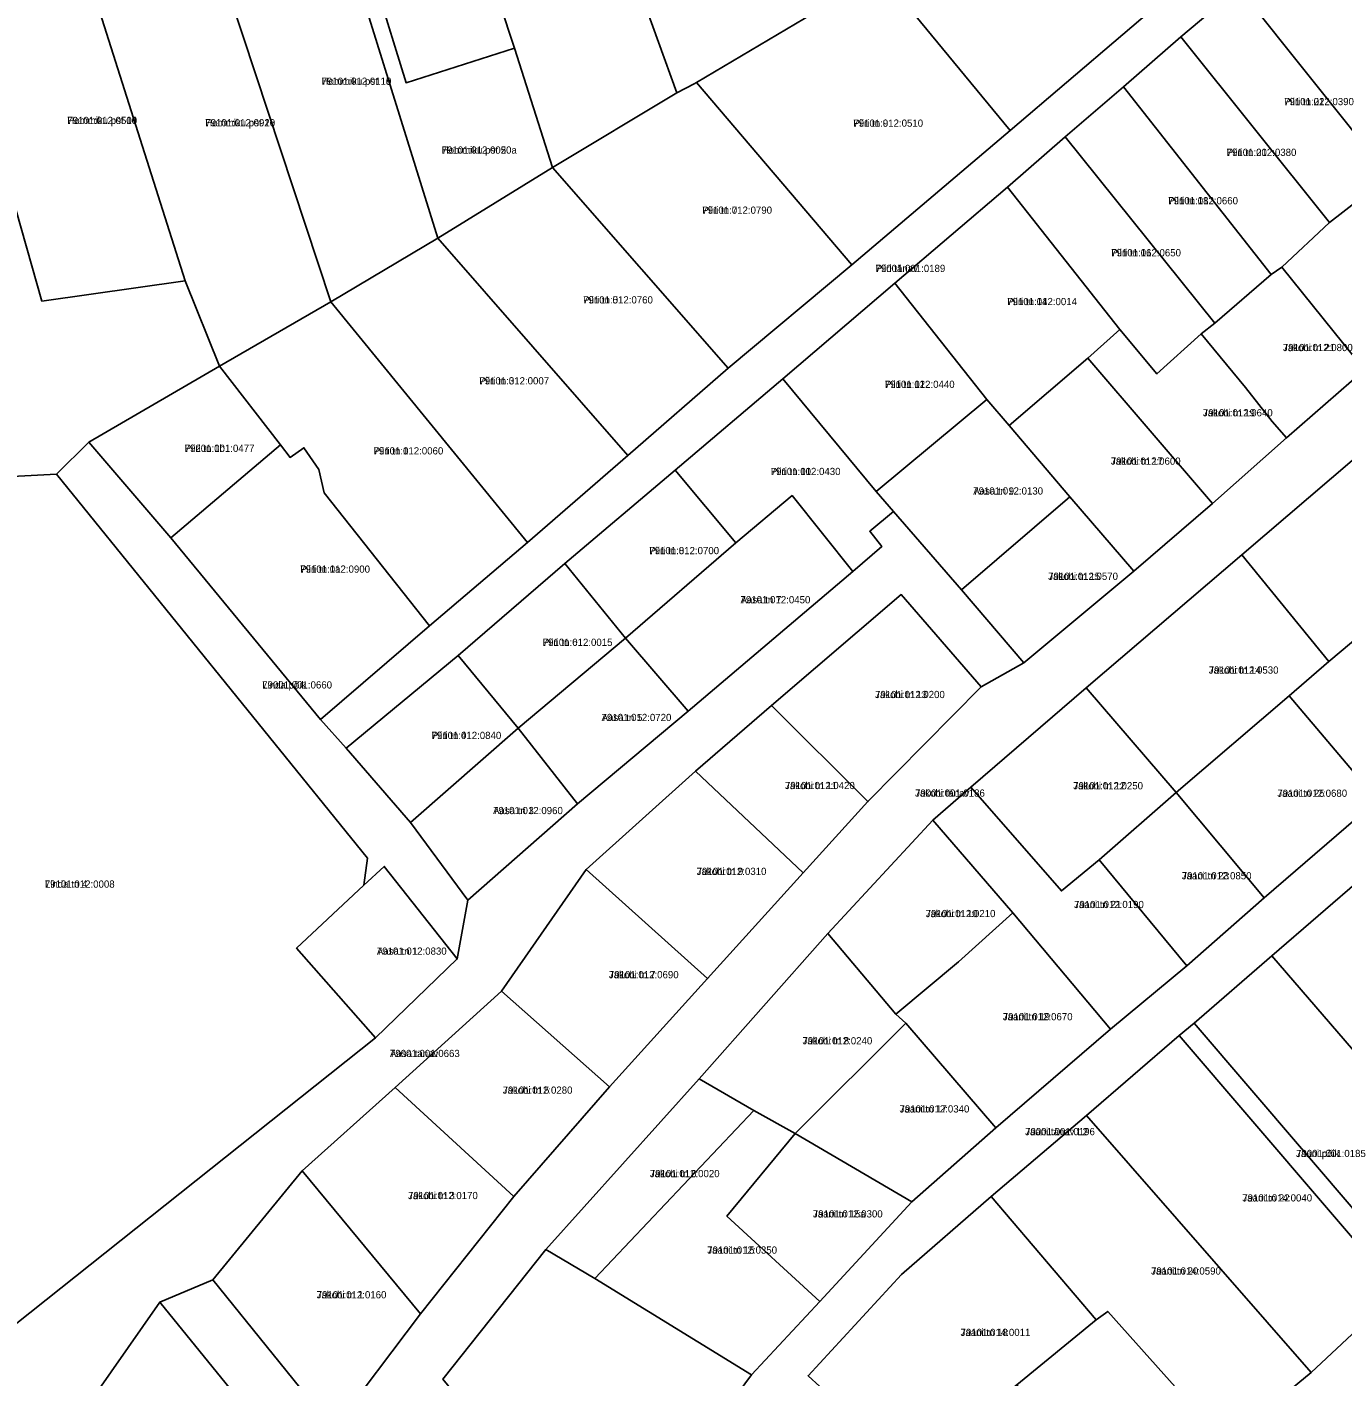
# Model space of a CAD drawing. Extents: x 587616 to 632239, y 6547421 to 6574977.
# Drawn here: x 612329 to 612602.3, y 6570710.7 to 6570991.1 of the extents above; entities that cross this region are included whole.
import ezdxf

# ---------------------------------------------------------------- set-up
doc = ezdxf.new("R2010")
doc.units = 0
for name, color, linetype in [('L_AADRESS', 7, 'Continuous'), ('PIIR', 7, 'Continuous'), ('TUNNUS', 7, 'Continuous')]:
    doc.layers.add(name, color=color, linetype=linetype)

msp = doc.modelspace()

# ---------------------------------------------------------------- linework, layer by layer
at = {"layer": 'PIIR'}
for points in [[(612389.94, 6570847.26), (612412.64, 6570866.69), (612433.02, 6570884.05), (612453.81, 6570902.08), (612474.71, 6570920.29), (612500.42, 6570941.76), (612533.3, 6570969.66), (612568.39, 6570999.66), (612614.03, 6571039.16), (612617.14, 6571030.36), (612593.08, 6571009.5), (612580.84, 6570999.28), (612568.76, 6570989.08), (612556.88, 6570978.73), (612544.75, 6570968.32), (612532.76, 6570957.89), (612509.3, 6570937.93), (612486.02, 6570918.07), (612463.66, 6570899.06), (612440.76, 6570879.66), (612418.55, 6570860.59), (612395.3, 6570841.33)], [(612478.97, 6571038.64), (612496.16, 6570996.2), (612468.11, 6570979.63), (612467.62, 6570979.34), (612464, 6570977.46), (612445, 6571030.17)], [(612430.31, 6570986.72), (612417.96, 6571024.07), (612445, 6571030.17), (612464, 6570977.46), (612438.2, 6570961.93)], [(612506.46, 6571002.17), (612513.42, 6571006.83), (612535.92, 6571019.94), (612550.68, 6571028.77), (612568.39, 6570999.66), (612533.3, 6570969.66)], [(612417.96, 6571024.07), (612430.31, 6570986.72), (612407.77, 6570979.56), (612395.44, 6571019.47)], [(612392.11, 6571018.7), (612414.38, 6570947.27), (612392.14, 6570934.06), (612365.99, 6571013.12)], [(612392.11, 6571018.7), (612395.44, 6571019.47), (612407.77, 6570979.56), (612430.31, 6570986.72), (612438.2, 6570961.93), (612414.38, 6570947.27)], [(612339.92, 6571007.58), (612365.99, 6571013.12), (612392.14, 6570934.06), (612368.95, 6570920.7), (612361.85, 6570938.43)], [(612361.85, 6570938.43), (612332.07, 6570934.19), (612312.85, 6571001.74), (612339.92, 6571007.58)], [(612593.08, 6571009.5), (612604.88, 6570994.7), (612616.39, 6570979.98), (612623.73, 6570970.6), (612611.71, 6570960.58), (612580.84, 6570999.28)], [(612252.57, 6570990.08), (612312.2, 6571004.01), (612312.85, 6571001.74), (612332.07, 6570934.19), (612361.85, 6570938.43), (612368.95, 6570920.7), (612341.84, 6570904.87), (612335.14, 6570898.25), (612273.14, 6570894.97)], [(612468.11, 6570979.63), (612496.16, 6570996.2), (612506.46, 6571002.17), (612533.3, 6570969.66), (612500.42, 6570941.76)], [(612580.84, 6570999.28), (612611.71, 6570960.58), (612605.79, 6570955.33), (612599.68, 6570950.51), (612568.76, 6570989.08)], [(612556.88, 6570978.73), (612568.76, 6570989.08), (612599.68, 6570950.51), (612589.74, 6570941.27), (612587.53, 6570939.73)], [(612464, 6570977.46), (612467.62, 6570979.34), (612468.11, 6570979.63), (612500.42, 6570941.76), (612474.71, 6570920.29), (612438.2, 6570961.93)], [(612556.88, 6570978.73), (612587.53, 6570939.73), (612575.82, 6570929.61), (612544.75, 6570968.32)], [(612544.75, 6570968.32), (612575.82, 6570929.61), (612573.01, 6570927.38), (612563.78, 6570919.07), (612556.06, 6570928.32), (612532.76, 6570957.89)], [(612438.2, 6570961.93), (612474.71, 6570920.29), (612453.81, 6570902.08), (612414.38, 6570947.27)], [(612532.76, 6570957.89), (612556.06, 6570928.32), (612549.43, 6570922.33), (612533.1, 6570908.38), (612528.47, 6570913.77), (612509.3, 6570937.93)], [(612599.68, 6570950.51), (612605.79, 6570955.33), (612623.43, 6570933.68), (612606.95, 6570919.88), (612589.74, 6570941.27)], [(612414.38, 6570947.27), (612453.81, 6570902.08), (612433.02, 6570884.05), (612392.14, 6570934.06)], [(612582.22, 6570916.21), (612573.01, 6570927.38), (612575.82, 6570929.61), (612587.53, 6570939.73), (612589.74, 6570941.27), (612606.95, 6570919.88), (612590.75, 6570905.76), (612587.73, 6570909.16)], [(612486.02, 6570918.07), (612509.3, 6570937.93), (612528.47, 6570913.77), (612505.42, 6570894.61)], [(612368.95, 6570920.7), (612392.14, 6570934.06), (612433.02, 6570884.05), (612412.64, 6570866.69), (612390.71, 6570894.39), (612389.66, 6570899.21), (612386.53, 6570903.72), (612383.64, 6570901.71), (612381.63, 6570904.32)], [(612556.06, 6570928.32), (612563.78, 6570919.07), (612573.01, 6570927.38), (612582.22, 6570916.21), (612587.73, 6570909.16), (612590.75, 6570905.76), (612575.34, 6570892.15), (612549.43, 6570922.33)], [(612341.84, 6570904.87), (612368.95, 6570920.7), (612381.63, 6570904.32), (612358.88, 6570885.02)], [(612533.1, 6570908.38), (612549.43, 6570922.33), (612575.34, 6570892.15), (612559, 6570878.1), (612545.72, 6570893.5)], [(612505.42, 6570894.61), (612509.02, 6570890.5), (612504.11, 6570886.39), (612506.63, 6570883.23), (612500.63, 6570878.04), (612487.97, 6570893.79), (612476.29, 6570884), (612463.66, 6570899.06), (612486.02, 6570918.07)], [(612509.02, 6570890.5), (612505.42, 6570894.61), (612528.47, 6570913.77), (612533.1, 6570908.38), (612545.72, 6570893.5), (612523.21, 6570874.23)], [(612420.6, 6570809.75), (612418.39, 6570797.51), (612403.21, 6570816.74), (612398.97, 6570812.81), (612399.71, 6570818.48), (612335.14, 6570898.25), (612341.84, 6570904.87), (612358.88, 6570885.02), (612389.94, 6570847.26), (612395.3, 6570841.33), (612408.65, 6570825.83)], [(612412.64, 6570866.69), (612389.94, 6570847.26), (612358.88, 6570885.02), (612381.63, 6570904.32), (612383.64, 6570901.71), (612386.53, 6570903.72), (612389.66, 6570899.21), (612390.71, 6570894.39)], [(612622.96, 6570879.59), (612615.37, 6570872.59), (612599.5, 6570859.29), (612581.45, 6570881.46), (612604.85, 6570901.47)], [(612335.14, 6570898.25), (612399.71, 6570818.48), (612398.97, 6570812.81), (612384.99, 6570799.78), (612401.38, 6570781.15), (612292.21, 6570694.33), (612263.99, 6570725.29), (612272.88, 6570759.5), (612277.84, 6570786.63), (612273.67, 6570884.71), (612273.14, 6570894.97)], [(612440.76, 6570879.66), (612463.66, 6570899.06), (612476.29, 6570884), (612453.38, 6570864.16)], [(612453.38, 6570864.16), (612476.29, 6570884), (612487.97, 6570893.79), (612500.63, 6570878.04), (612466.4, 6570849)], [(612523.21, 6570874.23), (612545.72, 6570893.5), (612559, 6570878.1), (612536.12, 6570859.04)], [(612549.06, 6570853.84), (612581.45, 6570881.46), (612599.5, 6570859.29), (612591.26, 6570852.2), (612567.82, 6570832.13)], [(612440.76, 6570879.66), (612453.38, 6570864.16), (612431.06, 6570845.45), (612418.55, 6570860.59)], [(612483.69, 6570850.19), (612510.65, 6570873.21), (612527.28, 6570854.08), (612503.75, 6570830.21)], [(612609.62, 6570830.53), (612591.26, 6570852.2), (612599.5, 6570859.29), (612615.37, 6570872.59), (612633.51, 6570850.98)], [(612431.06, 6570845.45), (612453.38, 6570864.16), (612466.4, 6570849), (612443.41, 6570829.72)], [(612408.65, 6570825.83), (612395.3, 6570841.33), (612418.55, 6570860.59), (612431.06, 6570845.45)], [(612525.1, 6570833.23), (612549.06, 6570853.84), (612567.82, 6570832.13), (612551.82, 6570818.11), (612543.94, 6570811.66)], [(612467.92, 6570836.5), (612483.69, 6570850.19), (612503.75, 6570830.21), (612490.29, 6570815.41)], [(612567.82, 6570832.13), (612591.26, 6570852.2), (612609.62, 6570830.53), (612586.07, 6570810.2)], [(612408.65, 6570825.83), (612431.06, 6570845.45), (612443.41, 6570829.72), (612420.6, 6570809.75)], [(612467.92, 6570836.5), (612490.29, 6570815.41), (612470.43, 6570793.43), (612445.15, 6570816.07)], [(612517.22, 6570826.32), (612525.1, 6570833.23), (612543.94, 6570811.66), (612551.82, 6570818.11), (612569.99, 6570796.06), (612554.12, 6570782.92), (612533.88, 6570807.11)], [(612567.82, 6570832.13), (612586.07, 6570810.2), (612569.99, 6570796.06), (612551.82, 6570818.11)], [(612533.88, 6570807.11), (612522.59, 6570796.94), (612509.51, 6570786.07), (612495.43, 6570802.77), (612517.22, 6570826.32)], [(612384.99, 6570799.78), (612398.97, 6570812.81), (612403.21, 6570816.74), (612418.39, 6570797.51), (612401.38, 6570781.15)], [(612445.15, 6570816.07), (612470.43, 6570793.43), (612450.02, 6570770.92), (612427.61, 6570790.85)], [(612606.95, 6570814.75), (612636, 6570780.77), (612652.62, 6570761.77), (612633.4, 6570745.18), (612587.65, 6570798.13)], [(612511.59, 6570784.17), (612509.51, 6570786.07), (612522.59, 6570796.94), (612533.88, 6570807.11), (612554.12, 6570782.92), (612530.34, 6570762.42)], [(612480.02, 6570766.01), (612468.69, 6570772.6), (612495.43, 6570802.77), (612509.51, 6570786.07), (612511.59, 6570784.17), (612488.64, 6570761.23)], [(612587.65, 6570798.13), (612633.4, 6570745.18), (612616.98, 6570731.13), (612571.51, 6570784.15)], [(612427.61, 6570790.85), (612450.02, 6570770.92), (612430.18, 6570748.16), (612405.48, 6570770.79)], [(612511.59, 6570784.17), (612530.34, 6570762.42), (612512.88, 6570747.05), (612488.64, 6570761.23)], [(612568.43, 6570781.61), (612571.51, 6570784.15), (612616.98, 6570731.13), (612613.91, 6570728.5)], [(612595.82, 6570711.62), (612549.18, 6570764.99), (612568.43, 6570781.61), (612613.91, 6570728.5)], [(612436.8, 6570737.15), (612468.69, 6570772.6), (612480.02, 6570766.01), (612446.97, 6570731.09)], [(612405.48, 6570770.79), (612430.18, 6570748.16), (612410.73, 6570723.8), (612386.15, 6570753.47)], [(612488.64, 6570761.23), (612474.44, 6570744.06), (612493.73, 6570726.37), (612479.57, 6570711.12), (612446.97, 6570731.09), (612480.02, 6570766.01)], [(612551.19, 6570722.55), (612529.34, 6570748.14), (612549.18, 6570764.99), (612595.82, 6570711.62), (612578.05, 6570696.88), (612553.56, 6570724.29)], [(612488.64, 6570761.23), (612512.88, 6570747.05), (612493.73, 6570726.37), (612474.44, 6570744.06)], [(612386.15, 6570753.47), (612410.73, 6570723.8), (612392.69, 6570699.82), (612367.62, 6570730.85)], [(612491.29, 6570710.9), (612510.72, 6570731.98), (612529.34, 6570748.14), (612551.19, 6570722.55), (612534.7, 6570709.05), (612516.82, 6570694.83), (612512.72, 6570690.2), (612493.77, 6570708.69)], [(612436.8, 6570737.15), (612446.97, 6570731.09), (612479.57, 6570711.12), (612448.78, 6570669.63), (612415.41, 6570710.19)], [(612379.4, 6570698.14), (612367.43, 6570681.8), (612339.86, 6570702.31), (612356.6, 6570726.21)], [(612551.19, 6570722.55), (612553.56, 6570724.29), (612578.05, 6570696.88), (612560.16, 6570681.11), (612534.7, 6570709.05)]]:
    msp.add_lwpolyline(points, close=True, dxfattribs=at)
for points in [[(612379.4, 6570698.14), (612356.6, 6570726.21), (612367.62, 6570730.85), (612392.69, 6570699.82), (612410.73, 6570723.8), (612430.18, 6570748.16), (612450.02, 6570770.92), (612470.43, 6570793.43), (612490.29, 6570815.41), (612503.75, 6570830.21), (612527.28, 6570854.08), (612536.12, 6570859.04), (612559, 6570878.1), (612575.34, 6570892.15), (612590.75, 6570905.76), (612606.95, 6570919.88)], [(612604.85, 6570901.47), (612581.45, 6570881.46), (612549.06, 6570853.84), (612525.1, 6570833.23), (612517.22, 6570826.32), (612495.43, 6570802.77), (612468.69, 6570772.6), (612436.8, 6570737.15), (612415.41, 6570710.19)], [(612292.21, 6570694.33), (612401.38, 6570781.15), (612418.39, 6570797.51), (612420.6, 6570809.75), (612443.41, 6570829.72), (612466.4, 6570849), (612500.63, 6570878.04), (612506.63, 6570883.23), (612504.11, 6570886.39), (612509.02, 6570890.5), (612523.21, 6570874.23), (612536.12, 6570859.04), (612527.28, 6570854.08), (612510.65, 6570873.21), (612483.69, 6570850.19), (612467.92, 6570836.5), (612445.15, 6570816.07), (612427.61, 6570790.85), (612405.48, 6570770.79), (612386.15, 6570753.47), (612367.62, 6570730.85), (612356.6, 6570726.21), (612339.86, 6570702.31)], [(612448.78, 6570669.63), (612479.57, 6570711.12), (612493.73, 6570726.37), (612512.88, 6570747.05), (612530.34, 6570762.42), (612554.12, 6570782.92), (612569.99, 6570796.06), (612586.07, 6570810.2), (612609.62, 6570830.53)], [(612606.95, 6570814.75), (612587.65, 6570798.13), (612571.51, 6570784.15), (612568.43, 6570781.61), (612549.18, 6570764.99), (612529.34, 6570748.14), (612510.72, 6570731.98), (612491.29, 6570710.9), (612493.77, 6570708.69)], [(612619.25, 6570719.17), (612601.37, 6570704.8), (612596.12, 6570700.23), (612561.96, 6570669.67), (612554.84, 6570661.14), (612538.11, 6570640.38), (612528.11, 6570648.18), (612531.38, 6570648.78), (612544.3, 6570664.7), (612560.16, 6570681.11), (612578.05, 6570696.88), (612595.82, 6570711.62), (612613.91, 6570728.5)]]:
    msp.add_lwpolyline(points, dxfattribs=at)

# ---------------------------------------------------------------- texts
at = {"layer": 'L_AADRESS'}
for s, p in [('Hommiku pst 18', (612390.19, 6570979.13)), ('Piiri tn 22', (612590.23, 6570974.9)), ('Hommiku pst 14', (612337.35, 6570970.98)), ('Hommiku pst 16', (612366.03, 6570970.5)), ('Piiri tn 9', (612500.7, 6570970.42)), ('Hommiku pst 20a', (612415.16, 6570964.83)), ('Piiri tn 20', (612578.28, 6570964.35)), ('Piiri tn 7', (612469.31, 6570952.34)), ('Piiri tn 18', (612566.14, 6570954.31)), ('Piiri tn 16', (612554.29, 6570943.5)), ('Piiri tänav', (612505.31, 6570940.24)), ('Piiri tn 5', (612444.55, 6570933.7)), ('Piiri tn 14', (612532.68, 6570933.35)), ('Jakobi tn 21', (612589.98, 6570923.8)), ('Piiri tn 3', (612422.98, 6570916.88)), ('Piiri tn 12', (612507.25, 6570916.15)), ('Jakobi tn 19', (612573.35, 6570910.24)), ('Piiri tn 1b', (612361.74, 6570902.86)), ('Piiri tn 1', (612400.99, 6570902.33)), ('Jakobi tn 17', (612554.22, 6570900.2)), ('Piiri tn 10', (612483.54, 6570898.05)), ('Aasa tn 9', (612525.63, 6570894)), ('Piiri tn 8', (612458.3, 6570881.61)), ('Piiri tn 1a', (612385.76, 6570877.76)), ('Jakobi tn 15', (612541.2, 6570876.27)), ('Aasa tn 7', (612477.27, 6570871.4)), ('Piiri tn 6', (612436.15, 6570862.55)), ('Jakobi tn 14', (612574.56, 6570856.79)), ('Linda põik', (612377.87, 6570853.7)), ('Jakobi tn 13', (612505.21, 6570851.71)), ('Aasa tn 5', (612448.39, 6570846.94)), ('Piiri tn 4', (612413.04, 6570843.21)), ('Jakobi tn 11', (612486.5, 6570832.8)), ('Jakobi tn 12', (612546.4, 6570832.75)), ('Jakobi tänav', (612513.53, 6570831.23)), ('Jaani tn 25', (612588.82, 6570831.2)), ('Aasa tn 3', (612425.83, 6570827.6)), ('Jakobi tn 9', (612468.14, 6570814.96)), ('Linda tn 4', (612332.69, 6570812.32)), ('Jaani tn 23', (612568.95, 6570814.05)), ('Jakobi tn 10', (612515.73, 6570806.2)), ('Jaani tn 21', (612546.57, 6570808.08)), ('Aasa tn 1', (612401.69, 6570798.39)), ('Jakobi tn 7', (612449.9, 6570793.5)), ('Jaani tn 19', (612531.76, 6570784.77)), ('Jakobi tn 8', (612490.14, 6570779.77)), ('Aasa tänav', (612404.41, 6570777.13)), ('Jakobi tn 5', (612427.83, 6570769.51)), ('Jaani tn 17', (612510.31, 6570765.61)), ('Jaani tänav L2', (612536.4, 6570760.89)), ('Jaani põik', (612592.7, 6570756.35)), ('Jakobi tn 6', (612458.41, 6570752.17)), ('Jakobi tn 3', (612408.16, 6570747.61)), ('Jaani tn 22', (612581.54, 6570747.12)), ('Jaani tn 15a', (612492.3, 6570743.8)), ('Jaani tn 15', (612470.35, 6570736.28)), ('Jaani tn 20', (612562.58, 6570731.93)), ('Jakobi tn 1', (612389.17, 6570726.99)), ('Jaani tn 18', (612522.99, 6570719.17))]:
    msp.add_text(s, height=1.5, dxfattribs=at).set_placement(p)
at = {"layer": 'TUNNUS'}
for s, p in [('79101:012:0110', (612390.19, 6570979.13)), ('79101:012:0390', (612590.23, 6570974.9)), ('79101:012:0500', (612337.35, 6570970.98)), ('79101:012:0920', (612366.03, 6570970.5)), ('79101:012:0510', (612500.7, 6570970.42)), ('79101:012:0050', (612415.16, 6570964.83)), ('79101:012:0380', (612578.28, 6570964.35)), ('79101:012:0790', (612469.31, 6570952.34)), ('79101:012:0660', (612566.14, 6570954.31)), ('79101:012:0650', (612554.29, 6570943.5)), ('79001:001:0189', (612505.31, 6570940.24)), ('79101:012:0760', (612444.55, 6570933.7)), ('79101:012:0014', (612532.68, 6570933.35)), ('79101:012:0800', (612589.98, 6570923.8)), ('79101:012:0007', (612422.98, 6570916.88)), ('79101:012:0440', (612507.25, 6570916.15)), ('79101:012:0640', (612573.35, 6570910.24)), ('79201:001:0477', (612361.74, 6570902.86)), ('79101:012:0060', (612400.99, 6570902.33)), ('79101:012:0600', (612554.22, 6570900.2)), ('79101:012:0430', (612483.54, 6570898.05)), ('79101:012:0130', (612525.63, 6570894)), ('79101:012:0700', (612458.3, 6570881.61)), ('79101:012:0900', (612385.76, 6570877.76)), ('79101:012:0570', (612541.2, 6570876.27)), ('79101:012:0450', (612477.27, 6570871.4)), ('79101:012:0015', (612436.15, 6570862.55)), ('79101:012:0530', (612574.56, 6570856.79)), ('79001:001:0660', (612377.87, 6570853.7)), ('79101:012:0200', (612505.21, 6570851.71)), ('79101:012:0720', (612448.39, 6570846.94)), ('79101:012:0840', (612413.04, 6570843.21)), ('79101:012:0420', (612486.5, 6570832.8)), ('79101:012:0250', (612546.4, 6570832.75)), ('79001:001:0186', (612513.53, 6570831.23)), ('79101:012:0680', (612588.82, 6570831.2)), ('79101:012:0960', (612425.83, 6570827.6)), ('79101:012:0310', (612468.14, 6570814.96)), ('79101:012:0008', (612332.69, 6570812.32)), ('79101:012:0850', (612568.95, 6570814.05)), ('79101:012:0190', (612546.57, 6570808.08)), ('79101:012:0210', (612515.73, 6570806.2)), ('79101:012:0830', (612401.69, 6570798.39)), ('79101:012:0690', (612449.9, 6570793.5)), ('79101:012:0670', (612531.76, 6570784.77)), ('79101:012:0240', (612490.14, 6570779.77)), ('79001:001:0663', (612404.41, 6570777.13)), ('79101:012:0280', (612427.83, 6570769.51)), ('79101:012:0340', (612510.31, 6570765.61)), ('79001:001:0196', (612536.4, 6570760.89)), ('79001:001:0185', (612592.7, 6570756.35)), ('79101:012:0020', (612458.41, 6570752.17)), ('79101:012:0170', (612408.16, 6570747.61)), ('79101:014:0040', (612581.54, 6570747.12)), ('79101:012:0300', (612492.3, 6570743.8)), ('79101:012:0350', (612470.35, 6570736.28)), ('79101:014:0590', (612562.58, 6570731.93)), ('79101:012:0160', (612389.17, 6570726.99)), ('79101:014:0011', (612522.99, 6570719.17))]:
    msp.add_text(s, height=1.5, dxfattribs=at).set_placement(p)

doc.saveas('drawing.dxf')
